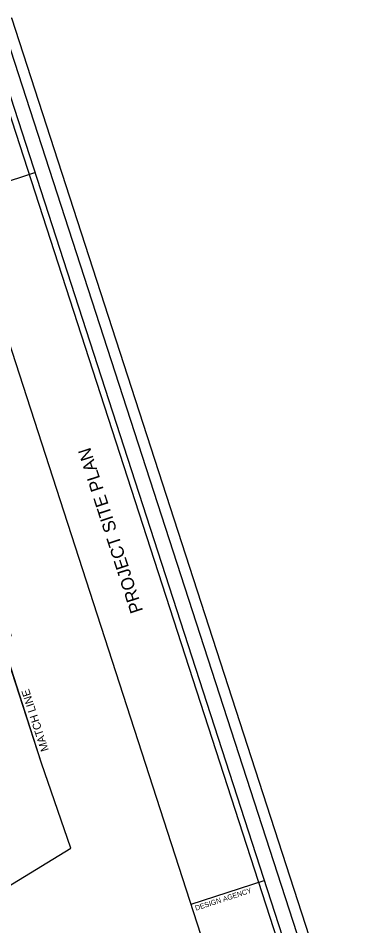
# Model space of a CAD drawing. Extents: x -468548933 to 3387700, y -306089263 to 1207014.
# Drawn here: x 1842053 to 1844053, y 535853 to 541159 of the extents above; entities that cross this region are included whole.
import ezdxf

# ---------------------------------------------------------------- set-up
doc = ezdxf.new("R2010")
doc.units = 0
for name, color, linetype in [('DT_X_Terrain_Ground_Line', 7, 'Continuous'), ('Level 63', 7, 'Continuous'), ('SC_Scratch1', 7, 'Continuous'), ('SH_Border', 7, 'Continuous'), ('SH_Cut_Line', 7, 'Continuous'), ('SH_Data', 7, 'Continuous')]:
    doc.layers.add(name, color=color, linetype=linetype)

msp = doc.modelspace()

# ---------------------------------------------------------------- linework, layer by layer
at = {"layer": 'DT_X_Terrain_Ground_Line'}
msp.add_line((1842189.4, 536805.1), (1841581.8, 538676.6), dxfattribs=at)
at = {"layer": 'Level 63'}
for points in [[(1832262, 537961.5), (1841962.9, 541110.9), (1844000.6, 534834.2), (1834299.8, 531684.7)], [(1834368.8, 531858.5), (1843842, 534934.1), (1841881.8, 540971.9), (1832408.6, 537896.3)]]:
    msp.add_lwpolyline(points, close=True, dxfattribs=at)
at = {"layer": 'SC_Scratch1'}
msp.add_lwpolyline([(1834448.4, 536360.5), (1835055.8, 534489.4), (1836664.2, 534206.2), (1839225.8, 534394.2), (1842361.7, 536308.3), (1842189.4, 536805.1), (1841581.8, 538676.6), (1840313.7, 539042.5), (1837357.7, 538260.2), (1834781, 538194.3), (1834403.1, 536496.4)], close=True, dxfattribs=at)
at = {"layer": 'SH_Border'}
for p, q in [((1843436.2, 534838.5), (1841490.8, 540830.6)), ((1841722.4, 540117.3), (1842150.4, 540256.3)), ((1843065.6, 535979.9), (1843493.6, 536118.8))]:
    msp.add_line(p, q, dxfattribs=at)
msp.add_lwpolyline([(1832787.9, 538005.2), (1841918.8, 540969.6), (1843864.2, 534977.5), (1834733.3, 532013.1)], close=True, dxfattribs=at)
at = {"layer": 'SH_Cut_Line'}
msp.add_lwpolyline([(1834351.6, 531731.5), (1844053.2, 534881.1), (1842015.1, 541158.6), (1832313.6, 538008.9)], close=True, dxfattribs=at)

# ---------------------------------------------------------------- texts
at = {"layer": 'DT_X_Terrain_Ground_Line'}
msp.add_text('MATCH LINE                  STA. 1765+00', height=46.8, rotation=107.9864, dxfattribs=at).set_placement((1842232.6, 536881.1))
at = {"layer": 'SH_Data'}
for s, height, rotation, p in [('PROJECT SITE PLAN', 75, 107.9864, (1842784.8, 537694.9)), ('DESIGN AGENCY', 30, 17.9864, (1843093.8, 535941.7))]:
    msp.add_text(s, height=height, rotation=rotation, dxfattribs=at).set_placement(p)

doc.saveas('drawing.dxf')
